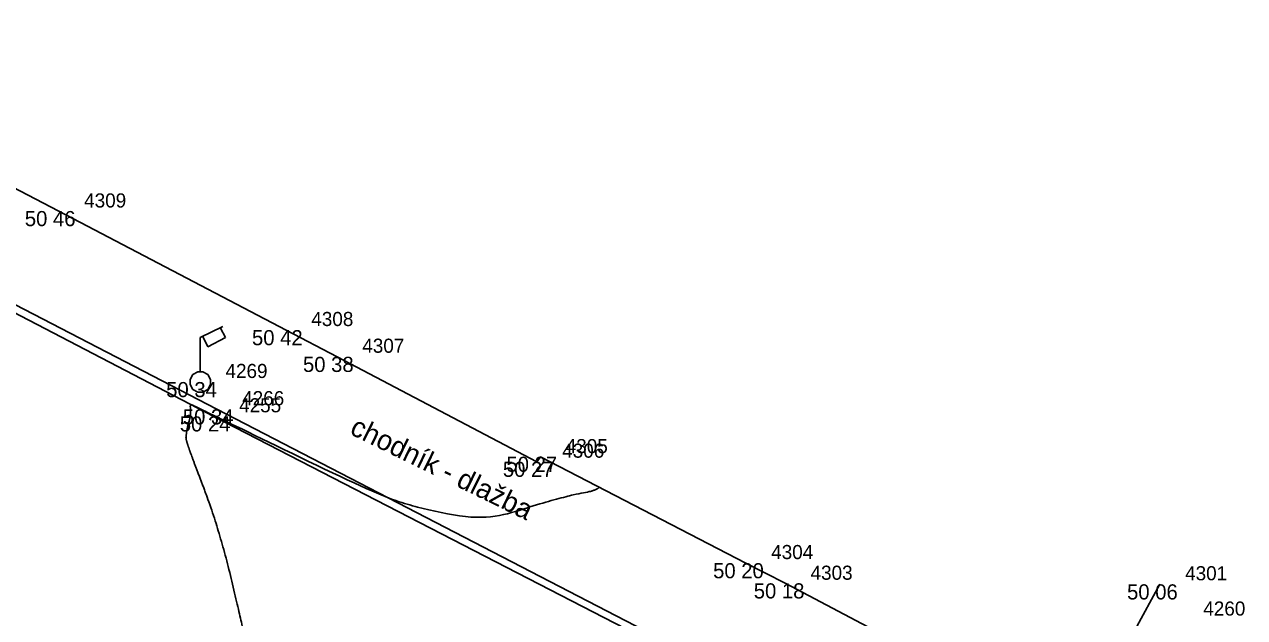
# Model space of a CAD drawing. Extents: x -704017 to -701500, y -1008977 to -1008450.
# Drawn here: x -701790.22 to -701766.05, y -1008928.82 to -1008917.06 of the extents above; entities that cross this region are included whole.
import ezdxf

# ---------------------------------------------------------------- set-up
doc = ezdxf.new("R2010")
doc.units = 0
for name, color, linetype in [('Z_body', 7, 'Continuous'), ('Z_body_cisla', 7, 'Continuous'), ('Z_body_vysky', 7, 'Continuous'), ('Z_budovy', 7, 'Continuous'), ('Z_komunikace', 7, 'Continuous'), ('Z_obruby', 7, 'Continuous'), ('Z_popis', 7, 'Continuous'), ('Z_site_znaky_VO', 7, 'Continuous'), ('Z_vrstevnice_vedlejsi', 7, 'Continuous'), ('Z_vstupy', 7, 'Continuous')]:
    doc.layers.add(name, color=color, linetype=linetype)

# ---------------------------------------------------------------- blocks, each defined once
blk = doc.blocks.new('POINT_DISPLAY')
blk.add_line((0, 0), (0, 0))
blk = doc.blocks.new('Z13')
for p, q in [((0, 0.88), (0.45, 1.1)), ((0.4, 1.07), (0.5, 0.88)), ((0, 0.2), (0, 0.88)), ((0.15, 0.7), (0.05, 0.9)), ((0.5, 0.88), (0.15, 0.7)), ((-0.2, 0.05), (-0.15, 0.15)), ((-0.2, -0.05), (-0.2, 0.05)), ((-0.15, 0.15), (-0.05, 0.2)), ((-0.05, 0.2), (0.05, 0.2)), ((0.05, 0.2), (0.15, 0.15)), ((0.15, 0.15), (0.2, 0.05)), ((0.2, 0.05), (0.2, -0.05)), ((-0.15, -0.15), (-0.2, -0.05)), ((-0.05, -0.2), (-0.15, -0.15)), ((0.05, -0.2), (-0.05, -0.2)), ((0.15, -0.15), (0.05, -0.2)), ((0.2, -0.05), (0.15, -0.15))]:
    blk.add_line(p, q)

msp = doc.modelspace()

# ---------------------------------------------------------------- linework, layer by layer
at = {"layer": 'Z_budovy'}
for p, q in [((-701789.54, -1008920.76), (-701796.65, -1008917.06)), ((-701785.04, -1008923.12), (-701789.54, -1008920.76)), ((-701780.07, -1008925.73), (-701784.03, -1008923.65)), ((-701780, -1008925.63), (-701780.07, -1008925.73)), ((-701775.93, -1008927.74), (-701780, -1008925.63)), ((-701769.38, -1008931.18), (-701775.15, -1008928.14)), ((-701767.73, -1008928.16), (-701769.38, -1008931.18))]:
    msp.add_line(p, q, dxfattribs=at)
at = {"layer": 'Z_komunikace'}
for p, q in [((-701797.62, -1008919.04), (-701786.47, -1008924.83)), ((-701786.47, -1008924.83), (-701776.64, -1008929.9))]:
    msp.add_line(p, q, dxfattribs=at)
at = {"layer": 'Z_obruby'}
for p, q in [((-701786.41, -1008924.69), (-701797.43, -1008918.98)), ((-701776.59, -1008929.77), (-701786.41, -1008924.69))]:
    msp.add_line(p, q, dxfattribs=at)
at = {"layer": 'Z_vrstevnice_vedlejsi'}
msp.add_open_spline([(-701780.37, -1008942.3), (-701779.663, -1008941.018), (-701779.619, -1008940.498), (-701779.622, -1008940.482), (-701779.992, -1008940.076), (-701780.22, -1008939.945), (-701782.116, -1008938.81), (-701782.385, -1008938.735), (-701783.015, -1008937.3), (-701783.273, -1008936.923), (-701783.853, -1008936.331), (-701784.027, -1008935.822), (-701784.036, -1008935.582), (-701784.106, -1008935.525), (-701783.661, -1008935.639), (-701783.182, -1008935.849), (-701783.401, -1008935.701), (-701784.062, -1008935.357), (-701785.982, -1008934.283), (-701788.263, -1008933.04), (-701785.923, -1008929.65), (-701785.816, -1008929.525), (-701785.823, -1008929.336), (-701786.355, -1008927.07), (-701787.003, -1008925.385), (-701787.033, -1008925.191), (-701786.912, -1008924.761), (-701786.955, -1008924.578), (-701786.813, -1008924.647), (-701786.464, -1008924.816), (-701781.758, -1008927.096), (-701779.49, -1008926.403), (-701778.887, -1008926.304), (-701778.837, -1008926.233)], degree=2, dxfattribs=at)
at = {"layer": 'Z_vstupy'}
for p, q in [((-701785.04, -1008923.12), (-701784.03, -1008923.65)), ((-701775.93, -1008927.74), (-701775.15, -1008928.14))]:
    msp.add_line(p, q, dxfattribs=at)

# ---------------------------------------------------------------- block references
at = {"layer": 'Z_body'}
for p in [(-701789.54, -1008920.76), (-701785.04, -1008923.12), (-701784.03, -1008923.65), (-701786.74, -1008924.15), (-701786.41, -1008924.69), (-701786.47, -1008924.83), (-701780, -1008925.63), (-701780.07, -1008925.73), (-701775.93, -1008927.74), (-701775.15, -1008928.14), (-701767.73, -1008928.16)]:
    msp.add_blockref('POINT_DISPLAY', p, dxfattribs=at)
at = {"layer": 'Z_site_znaky_VO'}
msp.add_blockref('Z13', (-701786.74, -1008924.15), dxfattribs=at)

# ---------------------------------------------------------------- texts
at = {"layer": 'Z_body_cisla'}
for s, p in [('4309', (-701789.04, -1008920.69)), ('4308', (-701784.54, -1008923.04)), ('4307', (-701783.53, -1008923.57)), ('4269', (-701786.24, -1008924.07)), ('4255', (-701785.97, -1008924.75)), ('4266', (-701785.91, -1008924.61)), ('4306', (-701779.57, -1008925.65)), ('4305', (-701779.5, -1008925.56)), ('4304', (-701775.43, -1008927.66)), ('4303', (-701774.65, -1008928.07)), ('4301', (-701767.23, -1008928.08)), ('4260', (-701766.87, -1008928.78))]:
    msp.add_text(s, height=0.28, dxfattribs=at).set_placement(p)
at = {"layer": 'Z_body_vysky'}
for s, p in [('50 46', (-701790.215, -1008921.06)), ('50 42', (-701785.715, -1008923.42)), ('50 38', (-701784.705, -1008923.95)), ('50 34', (-701787.415, -1008924.45)), ('50 34', (-701787.085, -1008924.99)), ('50 24', (-701787.145, -1008925.13)), ('50 27', (-701780.675, -1008925.93)), ('50 27', (-701780.745, -1008926.03)), ('50 20', (-701776.58, -1008928.04)), ('50 18', (-701775.775, -1008928.44)), ('50 06', (-701768.38, -1008928.46))]:
    msp.add_text(s, height=0.3, dxfattribs=at).set_placement(p)
at = {"layer": 'Z_popis'}
msp.add_text('chodník - dlažba', height=0.4, rotation=333.9, dxfattribs=at).set_placement((-701783.8, -1008925.17))

doc.saveas('drawing.dxf')
